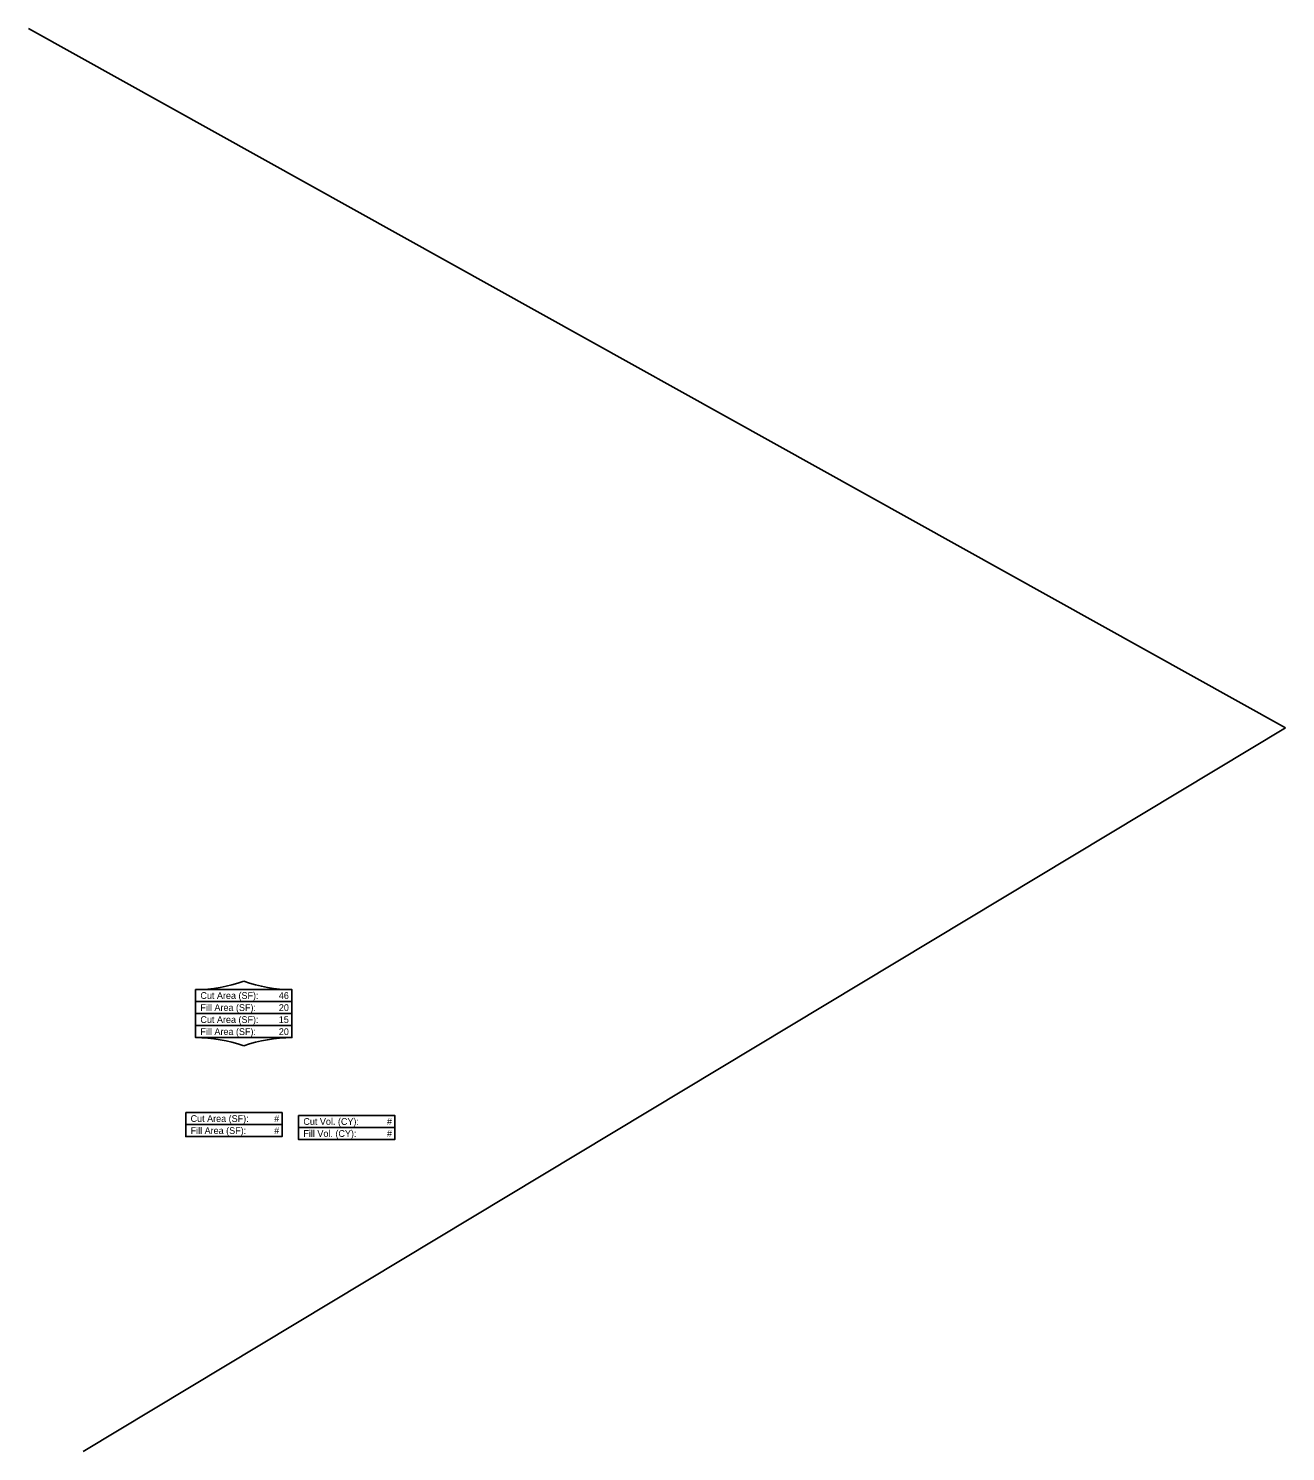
# Model space of a CAD drawing. Extents: x -475 to 76, y 0 to 417.
# Drawn here: x -442.54 to -416.42, y 366.16 to 395.75 of the extents above; entities that cross this region are included whole.
import ezdxf

# ---------------------------------------------------------------- set-up
doc = ezdxf.new("R2010")
doc.units = 0
for name, color, linetype in [('SC_Scratch1', 7, 'Continuous'), ('SC_Scratch10', 7, 'Continuous'), ('SH_Masking', 7, 'Continuous')]:
    doc.layers.add(name, color=color, linetype=linetype)

msp = doc.modelspace()

# ---------------------------------------------------------------- linework, layer by layer
at = {"layer": 'SC_Scratch1'}
for p, q in [((-439.07, 375.771), (-437.07, 375.771)), ((-439.07, 375.771), (-439.07, 375.271)), ((-437.07, 375.771), (-439.07, 375.771)), ((-439.07, 375.521), (-437.07, 375.521)), ((-437.07, 375.771), (-437.07, 375.271)), ((-439.07, 375.271), (-437.07, 375.271)), ((-439.07, 375.271), (-437.07, 375.271)), ((-439.07, 375.271), (-439.07, 374.771)), ((-437.07, 375.271), (-437.07, 374.771)), ((-439.07, 375.021), (-437.07, 375.021)), ((-439.07, 374.771), (-437.07, 374.771)), ((-437.07, 374.771), (-439.07, 374.771)), ((-439.274, 373.213), (-437.274, 373.213)), ((-439.274, 373.213), (-439.274, 372.713)), ((-437.274, 373.213), (-437.274, 372.713)), ((-436.93, 373.152), (-434.93, 373.152)), ((-436.93, 373.152), (-436.93, 372.652)), ((-434.93, 373.152), (-434.93, 372.652)), ((-439.274, 372.963), (-437.274, 372.963)), ((-436.93, 372.902), (-434.93, 372.902)), ((-439.274, 372.713), (-437.274, 372.713)), ((-436.93, 372.652), (-434.93, 372.652))]:
    msp.add_line(p, q, dxfattribs=at)
for centre, start, end in [((-439.07, 378.771), 270, 289.4712), ((-437.07, 378.771), 250.5288, 270), ((-439.07, 371.771), 70.5288, 90), ((-437.07, 371.771), 90, 109.4712)]:
    msp.add_arc(centre, 3, start, end, dxfattribs=at)
at = {"layer": 'SC_Scratch10'}
for p, q in [((-416.417, 381.215), (-442.544, 395.754)), ((-441.406, 366.165), (-416.417, 381.215))]:
    msp.add_line(p, q, dxfattribs=at)
at = {"layer": 'SH_Masking'}
for points in [[(-439.07, 375.771), (-437.07, 375.771), (-437.07, 375.271), (-439.07, 375.271)], [(-439.07, 375.271), (-437.07, 375.271), (-437.07, 374.771), (-439.07, 374.771)], [(-439.274, 373.213), (-437.274, 373.213), (-437.274, 372.713), (-439.274, 372.713)], [(-436.93, 373.152), (-434.93, 373.152), (-434.93, 372.652), (-436.93, 372.652)]]:
    msp.add_lwpolyline(points, close=True, dxfattribs=at)

# ---------------------------------------------------------------- texts
at = {"layer": 'SC_Scratch10'}
for s, p in [('Cut Area (SF):', (-438.97, 375.576)), ('46', (-437.34, 375.576)), ('Cut Area (SF):', (-438.97, 375.076)), ('Fill Area (SF):', (-438.97, 375.326)), ('20', (-437.34, 375.326)), ('15', (-437.341, 375.076)), ('Fill Area (SF):', (-438.97, 374.826)), ('20', (-437.34, 374.826)), ('Cut Area (SF):', (-439.174, 373.018)), ('#', (-437.437, 373.018)), ('Fill Area (SF):', (-439.174, 372.768)), ('#', (-437.437, 372.768)), ('Cut Vol. (CY):', (-436.83, 372.957)), ('Fill Vol. (CY):', (-436.83, 372.707)), ('#', (-435.093, 372.957)), ('#', (-435.093, 372.707))]:
    msp.add_text(s, height=0.14, dxfattribs=at).set_placement(p)

doc.saveas('drawing.dxf')
